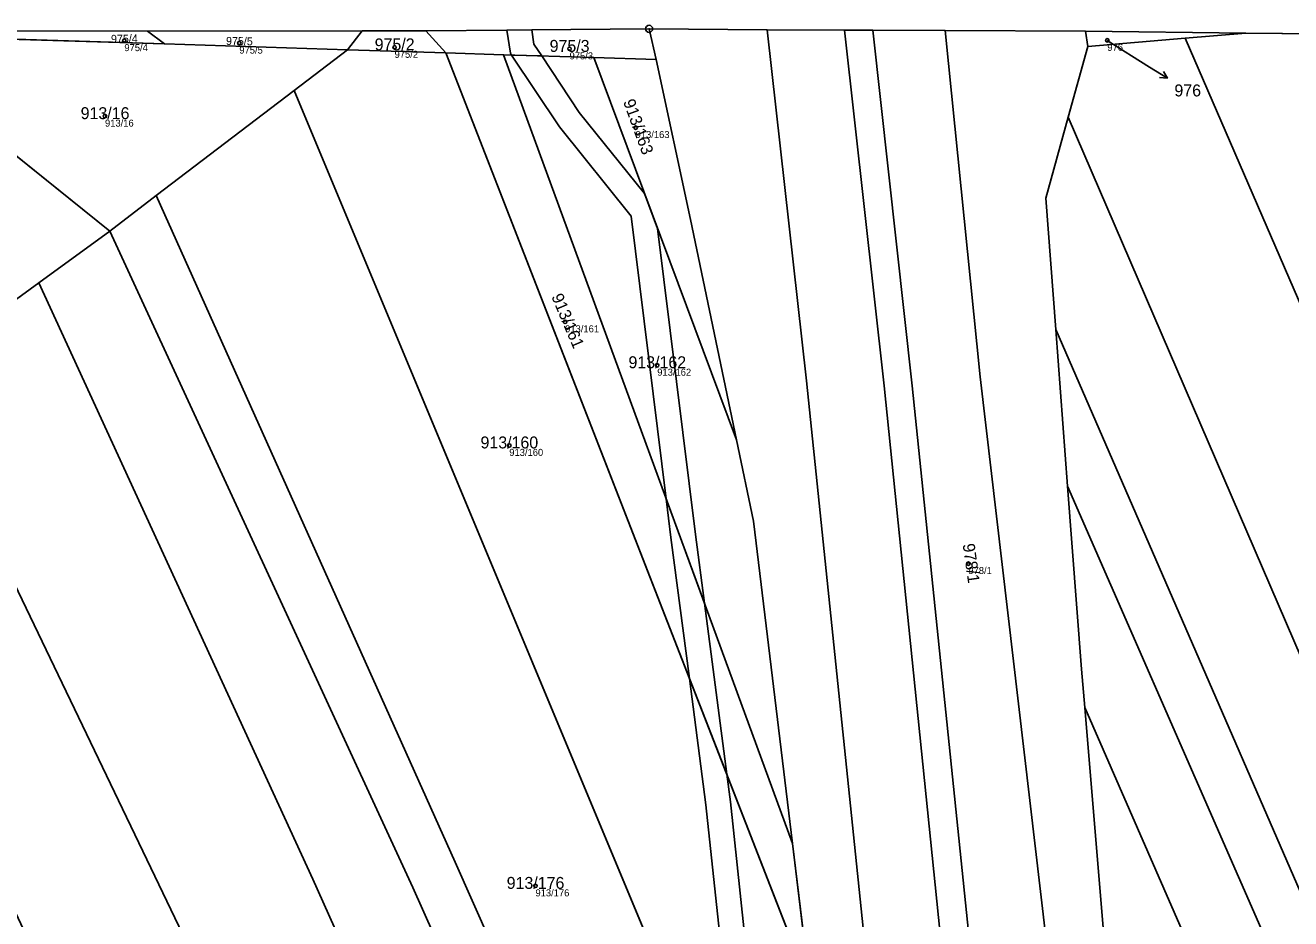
# Model space of a CAD drawing. Extents: x -603967 to -594699, y -1179315 to -1165625.
# Drawn here: x -596085.7 to -595905.4, y -1171230.5 to -1171103.2 of the extents above; entities that cross this region are included whole.
import ezdxf

# ---------------------------------------------------------------- set-up
doc = ezdxf.new("R2010")
doc.units = 0
for name, color, linetype in [('Definiční body', 7, 'Continuous'), ('Hranice parcel', 7, 'Continuous'), ('Parcelní čísla', 7, 'Continuous'), ('Polygon ku', 7, 'Continuous'), ('Polygon parcely', 7, 'Continuous'), ('Pop  PČ popisy', 7, 'Continuous'), ('Vnitřní kresba', 7, 'Continuous'), ('Věcná břemena k části', 7, 'Continuous'), ('Značky bodu BP', 7, 'Continuous')]:
    doc.layers.add(name, color=color, linetype=linetype)

msp = doc.modelspace()

# ---------------------------------------------------------------- linework, layer by layer
at = {"layer": 'Definiční body'}
for centre in [(-596071.62, -1171105.40994), (-596055.24, -1171105.75994), (-595931.57, -1171105.36994), (-596033.12, -1171106.35994), (-596008.19, -1171106.57994), (-596074.38, -1171116.15994), (-595998.78, -1171117.78994), (-596008.82, -1171145.45994), (-595995.7, -1171151.63994), (-596016.78, -1171163.05994), (-595951.37, -1171179.88994), (-596013.05, -1171225.79994)]:
    msp.add_circle(centre, 0.25, dxfattribs=at)
at = {"layer": 'Hranice parcel'}
for p, q in [((-596109.27, -1171103.99), (-596068.33, -1171104.03)), ((-596068.33, -1171104.03), (-596037.73, -1171104.01)), ((-596065.89, -1171105.88), (-596068.33, -1171104.03)), ((-596039.83, -1171106.7), (-596037.73, -1171104.01)), ((-596028.68, -1171104), (-596037.73, -1171104.01)), ((-596025.84, -1171107.14), (-596028.68, -1171104)), ((-595995.85, -1171108.1), (-595996.85, -1171103.72)), ((-595911.86, -1171104.32), (-595934.7, -1171104.05)), ((-595934.33, -1171106.26), (-595934.7, -1171104.05)), ((-596065.89, -1171105.88), (-596108.53, -1171104.54)), ((-596108.53, -1171104.54), (-596073.7, -1171132.54)), ((-596039.83, -1171106.7), (-596065.89, -1171105.88)), ((-595934.33, -1171106.26), (-595920.48, -1171105.06)), ((-595911.86, -1171104.32), (-595920.48, -1171105.06)), ((-595911.86, -1171104.32), (-595896.41, -1171104.5)), ((-596047.43, -1171112.49), (-596039.83, -1171106.7)), ((-596025.84, -1171107.14), (-596039.83, -1171106.7)), ((-595973.95, -1171240.26), (-596025.84, -1171107.14)), ((-596017.59, -1171107.41), (-596025.84, -1171107.14)), ((-595976.44, -1171219.75), (-596017.59, -1171107.41)), ((-596004.72, -1171107.82), (-596017.59, -1171107.41)), ((-595934.33, -1171106.26), (-595937.13, -1171116.31)), ((-595984.42, -1171162.25), (-596004.72, -1171107.82)), ((-595995.85, -1171108.1), (-596004.72, -1171107.82)), ((-595990.97, -1171130.87), (-595995.85, -1171108.1)), ((-596067.07, -1171127.48), (-596047.43, -1171112.49)), ((-596047.43, -1171112.49), (-595965.96, -1171307.91)), ((-596073.7, -1171132.54), (-596067.07, -1171127.48)), ((-595984.42, -1171162.25), (-595990.97, -1171130.87)), ((-596083.82, -1171139.91), (-596073.7, -1171132.54)), ((-596096.4, -1171149.06), (-596083.82, -1171139.91)), ((-595938.93, -1171146.55), (-595937.23, -1171168.86)), ((-595934.79, -1171200.37), (-595932.18, -1171231.77)), ((-595973.95, -1171240.26), (-595976.44, -1171219.75))]:
    msp.add_line(p, q, dxfattribs=at)
for points in [[(-596028.68, -1171104), (-596017.12, -1171103.9), (-596013.58, -1171103.87), (-595996.85, -1171103.72)], [(-595934.7, -1171104.05), (-595954.69, -1171103.98), (-595964.96, -1171103.92), (-595969.04, -1171103.91), (-595980.04, -1171103.85), (-595996.85, -1171103.72)], [(-595723.89, -1171569.04), (-595740.14, -1171507.64), (-595758.68, -1171456.67), (-595779.87, -1171408.64), (-595840.63, -1171289.32), (-595920.48, -1171105.06)], [(-595937.13, -1171116.31), (-595940.35, -1171127.84), (-595938.93, -1171146.55)], [(-595937.13, -1171116.31), (-595867.33, -1171278.16), (-595810.09, -1171390.59), (-595779.53, -1171460.24), (-595761.51, -1171511.94), (-595745.47, -1171572.3)], [(-595959.52, -1171367.11), (-595976.79, -1171329.16), (-595999.14, -1171279.57), (-596024.49, -1171222.44), (-596067.07, -1171127.48)], [(-595958.02, -1171381.61), (-596001.45, -1171291.16), (-596030.52, -1171226.02), (-596073.7, -1171132.54)], [(-595954.72, -1171423.44), (-595970.04, -1171391.75), (-596044.75, -1171224.83), (-596083.82, -1171139.91)], [(-595938.93, -1171146.55), (-595886.04, -1171268.09), (-595860.84, -1171321.14), (-595815.93, -1171409.47), (-595793.73, -1171462.56), (-595775.54, -1171515.3), (-595759.77, -1171571.89)], [(-595949.11, -1171495.65), (-595981.48, -1171413.82), (-596018.94, -1171331.7), (-596057.55, -1171244.68), (-596101.7, -1171152.82)], [(-595976.44, -1171219.75), (-595982, -1171173.85), (-595984.42, -1171162.25)], [(-595937.23, -1171168.86), (-595888.53, -1171280.15), (-595836.79, -1171383.1), (-595802.75, -1171460.7), (-595781.36, -1171523.54), (-595768.36, -1171571.65)], [(-595937.23, -1171168.86), (-595935.24, -1171194.95), (-595934.79, -1171200.37)], [(-595934.79, -1171200.37), (-595896.92, -1171287.07), (-595851.98, -1171375.1), (-595814.26, -1171460.9), (-595790.9, -1171529.83), (-595778.84, -1171571.35)]]:
    msp.add_lwpolyline(points, dxfattribs=at)
at = {"layer": 'Polygon ku'}
msp.add_lwpolyline([(-595896.41, -1171104.5), (-595911.86, -1171104.32), (-595934.7, -1171104.05), (-595954.69, -1171103.98), (-595964.96, -1171103.92), (-595969.04, -1171103.91), (-595980.04, -1171103.85), (-595996.85, -1171103.72), (-596013.58, -1171103.87), (-596017.12, -1171103.9), (-596028.68, -1171104), (-596037.73, -1171104.01), (-596068.33, -1171104.03), (-596109.27, -1171103.99)], dxfattribs=at)
at = {"layer": 'Polygon parcely'}
for points in [[(-596073.7, -1171132.54), (-596108.53, -1171104.54), (-596128.91, -1171103.9), (-596150.53, -1171103.84), (-596096.4, -1171149.06), (-596083.82, -1171139.91)], [(-596065.89, -1171105.88), (-596068.33, -1171104.03), (-596109.27, -1171103.99), (-596108.53, -1171104.54)], [(-596039.83, -1171106.7), (-596037.73, -1171104.01), (-596068.33, -1171104.03), (-596065.89, -1171105.88)], [(-596028.68, -1171104), (-596037.73, -1171104.01), (-596039.83, -1171106.7), (-596025.84, -1171107.14)], [(-595995.85, -1171108.1), (-595996.85, -1171103.72), (-596013.58, -1171103.87), (-596017.12, -1171103.9), (-596028.68, -1171104), (-596025.84, -1171107.14), (-596017.59, -1171107.41), (-596004.72, -1171107.82)], [(-595934.7, -1171104.05), (-595934.33, -1171106.26), (-595920.48, -1171105.06), (-595911.86, -1171104.32)], [(-596047.43, -1171112.49), (-596039.83, -1171106.7), (-596065.89, -1171105.88), (-596108.53, -1171104.54), (-596073.7, -1171132.54), (-596067.07, -1171127.48)], [(-595937.13, -1171116.31), (-595867.33, -1171278.16), (-595810.09, -1171390.59), (-595779.53, -1171460.24), (-595761.51, -1171511.94), (-595745.47, -1171572.3), (-595723.89, -1171569.04), (-595740.14, -1171507.64), (-595758.68, -1171456.67), (-595779.87, -1171408.64), (-595840.63, -1171289.32), (-595920.48, -1171105.06), (-595934.33, -1171106.26)], [(-595838.36, -1171241), (-595896.41, -1171104.5), (-595911.86, -1171104.32), (-595920.48, -1171105.06), (-595840.63, -1171289.32), (-595779.87, -1171408.64), (-595758.68, -1171456.67), (-595740.14, -1171507.64), (-595723.89, -1171569.04), (-595699.26, -1171565.31), (-595715.45, -1171505.43), (-595738.32, -1171444.49), (-595776.38, -1171363.21), (-595825.63, -1171270.04)], [(-595971.9, -1171257.14), (-595973.95, -1171240.26), (-596025.84, -1171107.14), (-596039.83, -1171106.7), (-596047.43, -1171112.49), (-595965.96, -1171307.91)], [(-595976.44, -1171219.75), (-596017.59, -1171107.41), (-596025.84, -1171107.14), (-595973.95, -1171240.26)], [(-595982, -1171173.85), (-595984.42, -1171162.25), (-596004.72, -1171107.82), (-596017.59, -1171107.41), (-595976.44, -1171219.75)], [(-595990.97, -1171130.87), (-595995.85, -1171108.1), (-596004.72, -1171107.82), (-595984.42, -1171162.25)], [(-595965.6, -1171310.98), (-595965.96, -1171307.91), (-596047.43, -1171112.49), (-596067.07, -1171127.48), (-596024.49, -1171222.44), (-595999.14, -1171279.57), (-595976.79, -1171329.16), (-595959.52, -1171367.11)], [(-595759.77, -1171571.89), (-595745.47, -1171572.3), (-595761.51, -1171511.94), (-595779.53, -1171460.24), (-595810.09, -1171390.59), (-595867.33, -1171278.16), (-595937.13, -1171116.31), (-595940.35, -1171127.84), (-595938.93, -1171146.55), (-595886.04, -1171268.09), (-595860.84, -1171321.14), (-595815.93, -1171409.47), (-595793.73, -1171462.56), (-595775.54, -1171515.3)], [(-595959.52, -1171367.11), (-595976.79, -1171329.16), (-595999.14, -1171279.57), (-596024.49, -1171222.44), (-596067.07, -1171127.48), (-596073.7, -1171132.54), (-596030.52, -1171226.02), (-596001.45, -1171291.16), (-595958.02, -1171381.61), (-595958.2, -1171379.31)], [(-595958.02, -1171381.61), (-596001.45, -1171291.16), (-596030.52, -1171226.02), (-596073.7, -1171132.54), (-596083.82, -1171139.91), (-596044.75, -1171224.83), (-595970.04, -1171391.75), (-595954.72, -1171423.44)], [(-595949.11, -1171495.65), (-595949.88, -1171484.89), (-595954.72, -1171423.44), (-595970.04, -1171391.75), (-596044.75, -1171224.83), (-596083.82, -1171139.91), (-596096.4, -1171149.06), (-596101.7, -1171152.82), (-596057.55, -1171244.68), (-596018.94, -1171331.7), (-595981.48, -1171413.82)], [(-595802.75, -1171460.7), (-595781.36, -1171523.54), (-595768.36, -1171571.65), (-595759.77, -1171571.89), (-595775.54, -1171515.3), (-595793.73, -1171462.56), (-595815.93, -1171409.47), (-595860.84, -1171321.14), (-595886.04, -1171268.09), (-595938.93, -1171146.55), (-595937.23, -1171168.86), (-595888.53, -1171280.15), (-595836.79, -1171383.1)], [(-595947.14, -1171580.49), (-595943.2, -1171579.93), (-595946.41, -1171533.18), (-595949.11, -1171495.65), (-595981.48, -1171413.82), (-596018.94, -1171331.7), (-596057.55, -1171244.68), (-596101.7, -1171152.82), (-596103.75, -1171154.27), (-596117.59, -1171165.05), (-596078.28, -1171248.34), (-596034.5, -1171347.07), (-595999.13, -1171425), (-595972.14, -1171496.95)], [(-595814.26, -1171460.9), (-595790.9, -1171529.83), (-595778.84, -1171571.35), (-595768.36, -1171571.65), (-595781.36, -1171523.54), (-595802.75, -1171460.7), (-595836.79, -1171383.1), (-595888.53, -1171280.15), (-595937.23, -1171168.86), (-595935.24, -1171194.95), (-595934.79, -1171200.37), (-595896.92, -1171287.07), (-595851.98, -1171375.1)], [(-595932.18, -1171231.77), (-595900.75, -1171302.3), (-595865.39, -1171372.86), (-595822.94, -1171467.24), (-595798.58, -1171542.52), (-595790.42, -1171571.02), (-595778.84, -1171571.35), (-595790.9, -1171529.83), (-595814.26, -1171460.9), (-595851.98, -1171375.1), (-595896.92, -1171287.07), (-595934.79, -1171200.37)]]:
    msp.add_lwpolyline(points, close=True, dxfattribs=at)
msp.add_lwpolyline([(-595932.18, -1171231.77), (-595934.79, -1171200.37), (-595935.24, -1171194.95), (-595937.23, -1171168.86), (-595938.93, -1171146.55), (-595940.35, -1171127.84), (-595937.13, -1171116.31), (-595934.33, -1171106.26), (-595934.7, -1171104.05), (-595954.69, -1171103.98), (-595964.96, -1171103.92), (-595969.04, -1171103.91), (-595980.04, -1171103.85), (-595996.85, -1171103.72), (-595995.85, -1171108.1), (-595990.97, -1171130.87), (-595984.42, -1171162.25), (-595982, -1171173.85), (-595976.44, -1171219.75), (-595973.95, -1171240.26)], dxfattribs=at)
at = {"layer": 'Pop  PČ popisy'}
for p, q in [((-595931.57, -1171105.37), (-595925.55, -1171109.18)), ((-595925.55, -1171109.18), (-595923.005, -1171110.77)), ((-595923.005, -1171110.77), (-595924.12, -1171110.664)), ((-595923.005, -1171110.77), (-595923.589, -1171109.815))]:
    msp.add_line(p, q, dxfattribs=at)
at = {"layer": 'Vnitřní kresba'}
for p, q in [((-595980.04, -1171103.85), (-595974.42, -1171153.88)), ((-595969.04, -1171103.91), (-595963.35, -1171154.56)), ((-595964.96, -1171103.92), (-595959.36, -1171154.56)), ((-595954.69, -1171103.98), (-595949.69, -1171153.3)), ((-595974.42, -1171153.88), (-595965.95, -1171235.87)), ((-595963.35, -1171154.56), (-595955.2, -1171234.5)), ((-595959.36, -1171154.56), (-595951.15, -1171234.19)), ((-595949.69, -1171153.3), (-595940.29, -1171233.48))]:
    msp.add_line(p, q, dxfattribs=at)
at = {"layer": 'Věcná břemena k části'}
for points in [[(-596016.6, -1171107.21), (-596016.44, -1171107.45), (-596012.15, -1171107.58), (-596013.26, -1171105.91), (-596013.58, -1171103.87), (-596017.12, -1171103.9)], [(-595994.42, -1171170.66), (-595988.98, -1171185.52), (-595990.26, -1171175.73), (-595995.65, -1171132.14), (-595997.5, -1171127.17), (-596006.8, -1171115.62), (-596012.15, -1171107.58), (-596016.44, -1171107.45), (-596009.62, -1171117.69), (-595999.4, -1171130.41)], [(-595993.74, -1171176.17), (-595991.11, -1171196.24), (-595985.78, -1171209.9), (-595988.98, -1171185.52), (-595994.42, -1171170.66)], [(-595988.75, -1171214.25), (-595984.42, -1171255.04), (-595983.16, -1171266.64), (-595978.41, -1171278.05), (-595980.94, -1171254.66), (-595985.27, -1171213.83), (-595985.78, -1171209.9), (-595991.11, -1171196.24)]]:
    msp.add_lwpolyline(points, close=True, dxfattribs=at)
at = {"layer": 'Značky bodu BP'}
for radius in [0.5, 0.0303]:
    msp.add_circle((-595996.85, -1171103.71988), radius, dxfattribs=at)

# ---------------------------------------------------------------- texts
at = {"layer": 'Definiční body'}
for s, p in [('975/4', (-596071.62, -1171106.899)), ('976', (-595931.57, -1171106.859)), ('975/5', (-596055.24, -1171107.249)), ('975/2', (-596033.12, -1171107.849)), ('975/3', (-596008.19, -1171108.069)), ('913/16', (-596074.38, -1171117.649)), ('913/163', (-595998.78, -1171119.279)), ('913/161', (-596008.82, -1171146.949)), ('913/162', (-595995.7, -1171153.129)), ('913/160', (-596016.78, -1171164.549)), ('978/1', (-595951.37, -1171181.379)), ('913/176', (-596013.05, -1171227.289))]:
    msp.add_text(s, height=0.999996, dxfattribs=at).set_placement(p)
at = {"layer": 'Parcelní čísla'}
for s, height, rotation, p in [('975/4', 1.14, 1, (-596073.516, -1171105.728)), ('975/5', 1.14, 359, (-596057.146, -1171106.011)), ('913/163', 1.699998, 290, (-596000.58, -1171114.085)), ('913/161', 1.699998, 293, (-596010.811, -1171141.855)), ('978/1', 1.699998, 278, (-595952.185, -1171177.14))]:
    msp.add_text(s, height=height, rotation=rotation, dxfattribs=at).set_placement(p)
for s, p in [('975/2', (-596035.956, -1171106.785)), ('975/3', (-596011.026, -1171107.005)), ('976', (-595922.01, -1171113.345)), ('913/16', (-596077.846, -1171116.585)), ('913/162', (-595999.796, -1171152.065)), ('913/160', (-596020.876, -1171163.485)), ('913/176', (-596017.146, -1171226.225))]:
    msp.add_text(s, height=1.699998, dxfattribs=at).set_placement(p)

doc.saveas('drawing.dxf')
